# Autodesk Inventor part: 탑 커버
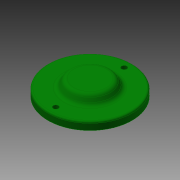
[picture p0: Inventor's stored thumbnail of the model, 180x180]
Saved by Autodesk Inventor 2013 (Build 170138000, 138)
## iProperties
Created: 2017-05
Part Number: 탑 커버
Material: 알루미늄 6061
Document SubType Name: Modeling
Designer: mduedu
Density: 1 g/cm^3
Author: mduedu
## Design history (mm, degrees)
sketch "스케치1"
  geometry: C1 r 27 at (0, 0); 1 further point
  constraints: 1 centre point, 1 coincident
  dimensions: "d31" = 54 diameter of C1
extrude "돌출1" new body sketch "스케치1" distance "d2" = 5; taper "d3" = 0 deg
sketch "스케치2"
  geometry: C1 r 15 at (0, 0); 1 further point
  constraints: 1 centre point, 1 coincident
  dimensions: "d5" = 30 diameter of C1
extrude "돌출2" join sketch "스케치2" distance "d6" = 5; taper "d7" = -30 deg
sketch "스케치3"
  geometry: C1 r 16 at (0, 0); 1 further point
  constraints: 1 centre point, 1 coincident
  dimensions: "d32" = 32 diameter of C1
extrude "돌출3" join sketch "스케치3" distance "d10" = 3; taper "d11" = 0 deg
sketch "스케치4"
  geometry: C1 r 16 at (0, 0) reference; C2 r 13 at (0, 0); 1 further point
  constraints: 1 centre point
  dimensions: "d33" = 3 radial gap between concentric circles of C2 C1
extrude "돌출4" cut sketch "스케치4" distance "d14" = 6; taper "d15" = 0 deg
chamfer "모따기1" distance "d16" = 1; stored, may be unused: second distance "d17" = 2, angle "d18" = 45 deg
fillet "모깎기3" dims "d19" = 3
fillet "모깎기4" dims "d20" = 1
fillet "모깎기5" dims "d21" = 1
sketch "스케치5" dims "d34" = 44
  geometry: C1 r 27 at (0, 0) reference; 2 further points
  constraints: 2 vertical alignment, 1 coincident, 2 other
hole "구멍2" sketch "스케치5" at (0, 22) diameter "d35" = 3.4; stored, may be unused: countersink angle "d39" = 90 deg, drill point angle "d41" = 118 deg; dims "d36" = 6, "d37" = 4, "d38" = 2, "d40" = 8
node "솔리드1"
pattern_circular "원형 패턴1" dims angle "d43" = 360 deg
node "투영된 루프2"
